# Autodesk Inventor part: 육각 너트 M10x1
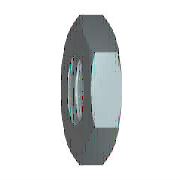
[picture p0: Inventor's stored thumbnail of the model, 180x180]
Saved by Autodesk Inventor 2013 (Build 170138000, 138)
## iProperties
Created: 2012-02
Part Number: 육각 너트 M10x1
Material: 스테인리스강
Description: 6각 가는 너트(모따기) - 제품 등급 A 및 B
Document SubType Name: Modeling
Standard: ISO 4035
Designer: mdu-01
Standard Revision: Third edition 1999-08-15
Standards Organization: ISO
Language: ko-KR
Size Designation: M10
Categories: <MemberInstance><Categories><Category DisplayName="조임쇠" InternalName="e4da775c-781d-43d5-af7c-5136215cf5a6" Mnemonic="FSTN"><Category DisplayName="너트" InternalN
Density: 7.75 g/cm^3
IsCustomPart: 1
Author: mdu-01
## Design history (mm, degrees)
sketch "스케치1"
  geometry: L1 (-9.238, 0)-(-4.619, 8); L2 (-4.619, 8)-(4.619, 8); L3 (4.619, 8)-(9.238, 0); L4 (9.238, 0)-(4.619, -8); L5 (4.619, -8)-(-4.619, -8); L6 (-4.619, -8)-(-9.238, 0); 2 further points
  constraints: 12 end point, 1 coincident, 1 horizontal, 11 other
  dimensions: "d0" = 18.47521 distance of L3.end L1.start (= 1.1547 x SW)
extrude "본체" new body sketch "스케치1" distance "d1" = 5 (= KOH); taper "d2" = 0 deg
sketch "스케치2"
  geometry: L1 (0, 4.619)-(0, 9.238) reference; L2 (0, 9.238)-(5, 9.238) reference; L3 (5, 4.619)-(5, 9.238) reference; L4 (-1, 0)-(6, 0) reference; L5 (1.119, 9.238)-(0, 7.3); L6 (3.881, 9.238)-(5, 7.3)
  constraints: 4 end point, 4 point on line
  dimensions: "d3" = 30 deg angle of L1 L5 (= ANG1); "d4" = 30 deg angle of L3 L6 (= ANG2); "d5" = 14.6 diameter of L5.end L4 (= SW0); "d6" = 14.6 diameter of L6.end L4 (= SW01)
revolve "모따기1" sketch "스케치2" stored, may be unused: angle "d7" = 90 deg
sketch "스케치3"
  geometry: 4 further points
  constraints: 1 coincident, 1 other
hole "스레드" sketch "스케치3" at (0, 0) diameter "d25" = 8.917; stored, may be unused: countersink angle "d29" = 82 deg, drill point angle "d31" = 118 deg; dims "d26" = 6, "d27" = 4, "d28" = 2, "d30" = 8
workaxis "Work Axis1"
workplane "Work Plane1"
body "Solid1"
chamfer "모따기2" distance "d8" = 0.8119 (= -0.5 x GD1 + 0.5 x NND); stored, may be unused: angle "d9" = 30 deg, second distance "d40" = 0.8119 (= -0.5 x GD1 + 0.5 x NND)
chamfer "모따기3" distance "d10" = 0.8119 (= -0.5 x GD1 + 0.5 x NND); stored, may be unused: angle "d11" = 30 deg, second distance "d41" = 0.8119 (= -0.5 x GD1 + 0.5 x NND)
other parameters: "ANG1" = 30 deg [user parameter; used in 1 equation term], "ANG2" = 30 deg [user parameter; used in 1 equation term], "KOH" = 5 [user parameter; used in 1 equation term], "SW" = 16 [user parameter; used in 2 equation terms], "SW0" = 14.6 [user parameter; used in 2 equation terms], "SW01" = 14.6 (= SW0) [user parameter; used in 1 equation term], "GD1" = 8.3762 (computed from THREADDIA, PTC, TOA) [user parameter; used in 4 equation terms], "d13" = 0, "d14" = 0, "d39" = 0, "d42" = 0, "GUL" = 0.8119 (= 0.541266 x PTC) [user parameter], "TPU" = 6.66667 (computed from PTC) [user parameter], "TOA" = 30 deg [user parameter; used in 1 equation term], "PTC" = 1.5 [user parameter; used in 4 equation terms], "E0" = 18.48 (= 1.155 x SW) [user parameter], "GAL" = 0.8119 (= 0.541266 x PTC) [user parameter]
